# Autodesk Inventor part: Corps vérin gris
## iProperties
Shininess: 20.0
Angle Display Precision: 2
Document Length Units: 11269
Document Angle Units: 11279
Document Time Units: 11290
Document Mass Units: 11283
Document Length Units Precision: 3
Document Angle Units Precision: 2
Created: 2002-09
Part Number: Corps vérin gris
Material: Par défaut
Document SubType Name: Modélisation
Designer: administrateur
Density: 0.0
Volumn: 0.0
Area: 0.0
PropertySet Name: Model Information
Control State: 0
Master: False
Checked Out: False
Author: administrateur
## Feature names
1. Extrusion1
2. Chanfrein1 [Chamfer]
3. Chanfrein2 [Chamfer]
4. Chanfrein3 [Chamfer]
5. Chanfrein4 [Chamfer]
6. Congé1 [Fillet]
7. Congé2 [Fillet]
